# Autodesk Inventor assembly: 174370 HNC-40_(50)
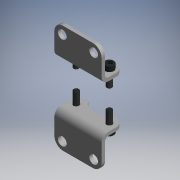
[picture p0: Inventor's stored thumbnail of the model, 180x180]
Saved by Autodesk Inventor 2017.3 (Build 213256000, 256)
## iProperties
Category: PARTsolutions
Company: FESTO
Part Number: 174370 HNC-40_(50)
Catalog Web Link: www.cadenas.de
Description: HNC-Foot mounting
Vendor: FESTO
Document SubType Name: Assembly
Designer: partserver
Manufacturer: FESTO
Mass: 193 g
Surface Area: 157.635 cm^2
Volume: 24.344 cm^3
Density: 7.92804 g/cm^3
Title: 174370 HNC-40
Author: Cadenas PARTsolutions
Comments: Foot mounting
PSOL_IDENT_0: {ATYP=ASSISTANT},{DATA=script=$CADENAS_DATA/23d-libs/festo/webfesto.vbb&M_FAMILY=HNC&M_GROUP=01&M_PA
PSOL_IDENT_1: RTNO=174370&IDCODE1=HNC-40&IDCODE2=&customer_number_cns=&MATES=1&LOD=HI&LOCKERP=0&SINGLEPART=1}
NB: 174370 HNC-40_(50)
NN: HNC
NT: Foot mounting
NBSYN: $TNR. $TYP._($DIST.)
LINA: 174370 HNC-40
CATALOG: Festo
TNR: 174370
TYP: HNC-40
DIST: 50
AB: 10
AH: 36
AW: 37
AT: 4
AU: 28
D2: 6.6
E: 54
LG: 18.5
R1: 17.5
R2: 8
TG: 38
TG2: 19
TR: 36
CNSMASSEXACT: 0.193
SUPPLIER: FESTO
ARTICLENO: 174370 HNC-40_(50)
BOMINFO: 174370 HNC-40
CREATOR: CADENAS GmbH
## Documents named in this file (3)
- e:\temp\worker_16\temp\exporttempdir_5136_38_6GOdT\format_0\174370 HNC-40_(50).iam
- e:\temp\worker_16\temp\exporttempdir_5136_38_6GOdT\format_0\174370 HNC-40---(F).ipt
- e:\temp\worker_16\temp\exporttempdir_5136_38_6GOdT\format_0\DIN-912 - M6x18(F).ipt
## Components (6 placed, 2 different names)
1. 174370 HNC-40---(F):1 — HNC_1_Z@1 <-> HNC_1_Z@2, HNC_1_YZ@1 <-> HNC_1_YZ@2, HNC_3_XY@1 <-> ANBAU_XY@5, HNC_3_Z@1 <-> ANBAU_Z@5, HNC_2_XY@1 <-> ANBAU_XY@6, HNC_2_Z@1 <-> ANBAU_Z@6, HNC_2_YZ@1 <-> ANBAU_YZ@6
2. 174370 HNC-40---(F):2 — HNC_1_Z@1 <-> HNC_1_Z@2, HNC_1_YZ@1 <-> HNC_1_YZ@2, HNC_3_XY@2 <-> ANBAU_XY@3, HNC_3_Z@2 <-> ANBAU_Z@3, HNC_2_XY@2 <-> ANBAU_XY@4, HNC_2_Z@2 <-> ANBAU_Z@4
3. DIN-912 - M6x18(F):1 — HNC_3_XY@2 <-> ANBAU_XY@3, HNC_3_Z@2 <-> ANBAU_Z@3
4. DIN-912 - M6x18(F):2 — HNC_2_XY@2 <-> ANBAU_XY@4, HNC_2_Z@2 <-> ANBAU_Z@4
5. DIN-912 - M6x18(F):3 — HNC_3_XY@1 <-> ANBAU_XY@5, HNC_3_Z@1 <-> ANBAU_Z@5
6. DIN-912 - M6x18(F):4 — HNC_2_XY@1 <-> ANBAU_XY@6, HNC_2_Z@1 <-> ANBAU_Z@6, HNC_2_YZ@1 <-> ANBAU_YZ@6
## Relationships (11: Mate 5, Flush 4, Angle 2)
- HNC_1_Z@1 <-> HNC_1_Z@2 [Mate]: 174370 HNC-40---(F):1 ↔ 174370 HNC-40---(F):2
- HNC_1_YZ@1 <-> HNC_1_YZ@2 [Angle]: 174370 HNC-40---(F):1 ↔ 174370 HNC-40---(F):2
- HNC_3_XY@2 <-> ANBAU_XY@3 [Flush]: 174370 HNC-40---(F):2 ↔ DIN-912 - M6x18(F):1
- HNC_3_Z@2 <-> ANBAU_Z@3 [Mate]: 174370 HNC-40---(F):2 ↔ DIN-912 - M6x18(F):1
- HNC_2_XY@2 <-> ANBAU_XY@4 [Flush]: 174370 HNC-40---(F):2 ↔ DIN-912 - M6x18(F):2
- HNC_2_Z@2 <-> ANBAU_Z@4 [Mate]: 174370 HNC-40---(F):2 ↔ DIN-912 - M6x18(F):2
- HNC_3_XY@1 <-> ANBAU_XY@5 [Flush]: 174370 HNC-40---(F):1 ↔ DIN-912 - M6x18(F):3
- HNC_3_Z@1 <-> ANBAU_Z@5 [Mate]: 174370 HNC-40---(F):1 ↔ DIN-912 - M6x18(F):3
- HNC_2_XY@1 <-> ANBAU_XY@6 [Flush]: 174370 HNC-40---(F):1 ↔ DIN-912 - M6x18(F):4
- HNC_2_Z@1 <-> ANBAU_Z@6 [Mate]: 174370 HNC-40---(F):1 ↔ DIN-912 - M6x18(F):4
- HNC_2_YZ@1 <-> ANBAU_YZ@6 [Angle]: 174370 HNC-40---(F):1 ↔ DIN-912 - M6x18(F):4
